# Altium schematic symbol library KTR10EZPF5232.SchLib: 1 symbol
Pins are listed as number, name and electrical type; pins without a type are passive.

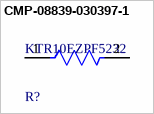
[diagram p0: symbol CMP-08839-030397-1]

## CMP-08839-030397-1
designator R?, comment KTR10EZPF5232
Res Thick Film 0805 52.3kΩ 1% 0.125W ±100ppm/°C Automotive Paper T/R; Max Power Dissipation: 125mW; Resistance: 52.3kR
footprint FP-KTR10-IPC_B
footprint FP-KTR10-IPC_A
footprint FP-KTR10-IPC_C
footprint FP-KTR10-MFG
pins: 1, 2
